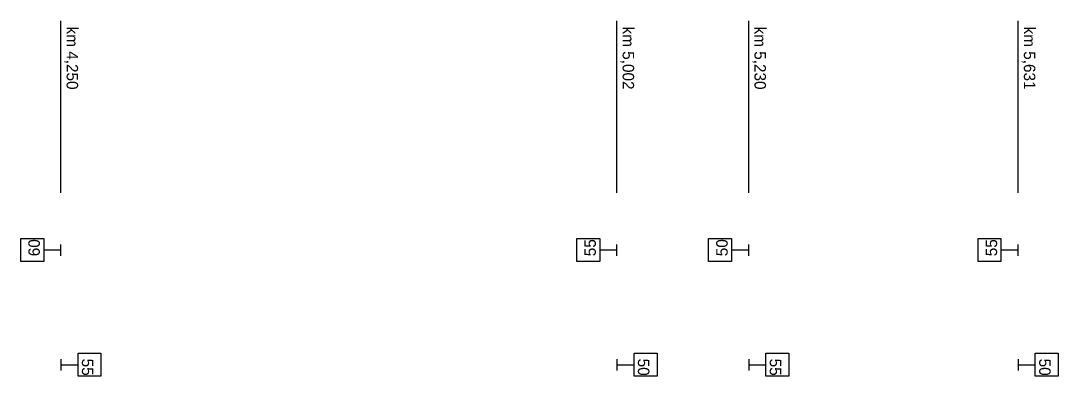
# Model space of a CAD drawing. Extents: x -591 to 5777, y 380 to 2087.
# Drawn here: x 2343 to 2524, y 1988 to 2050 of the extents above; entities that cross this region are included whole.
import ezdxf

# ---------------------------------------------------------------- set-up
doc = ezdxf.new("R2010")
doc.units = 0
doc.layers.add('rychlostník', color=7, linetype='Continuous')

msp = doc.modelspace()

# ---------------------------------------------------------------- linework, layer by layer
at = {"layer": 'rychlostník'}
for p, q in [((2350, 2020), (2350, 2050)), ((2447, 2020), (2447, 2050)), ((2447, 2020), (2447, 2050)), ((2470, 2020), (2470, 2050)), ((2470, 2020), (2470, 2050)), ((2517, 2020), (2517, 2050)), ((2517, 2020), (2517, 2050)), ((2343, 2008), (2343, 2012)), ((2343, 2012), (2347, 2012)), ((2347, 2012), (2347, 2008)), ((2350, 2009), (2350, 2011)), ((2440, 2008), (2440, 2012)), ((2440, 2012), (2444, 2012)), ((2444, 2012), (2444, 2008)), ((2447, 2009), (2447, 2011)), ((2463, 2008), (2463, 2012)), ((2463, 2012), (2467, 2012)), ((2467, 2012), (2467, 2008)), ((2470, 2009), (2470, 2011)), ((2510, 2008), (2510, 2012)), ((2510, 2012), (2514, 2012)), ((2514, 2012), (2514, 2008)), ((2517, 2009), (2517, 2011)), ((2350, 2010), (2347, 2010)), ((2442.33, 2010.09), (2442.33, 2010.09)), ((2447, 2010), (2444, 2010)), ((2465.33, 2010.09), (2465.33, 2010.09)), ((2470, 2010), (2467, 2010)), ((2512.33, 2010.09), (2512.33, 2010.09)), ((2517, 2010), (2514, 2010)), ((2347, 2008), (2343, 2008)), ((2444, 2008), (2440, 2008)), ((2467, 2008), (2463, 2008)), ((2514, 2008), (2510, 2008)), ((2353, 1992), (2357, 1992)), ((2353, 1988), (2353, 1992)), ((2357, 1992), (2357, 1988)), ((2450, 1992), (2454, 1992)), ((2450, 1988), (2450, 1992)), ((2454, 1992), (2454, 1988)), ((2473, 1992), (2477, 1992)), ((2473, 1988), (2473, 1992)), ((2477, 1992), (2477, 1988)), ((2520, 1992), (2524, 1992)), ((2520, 1988), (2520, 1992)), ((2524, 1992), (2524, 1988)), ((2350, 1991), (2350, 1989)), ((2350, 1990), (2353, 1990)), ((2447, 1991), (2447, 1989)), ((2447, 1990), (2450, 1990)), ((2451.67, 1989.91), (2451.67, 1989.91)), ((2470, 1991), (2470, 1989)), ((2470, 1990), (2473, 1990)), ((2474.67, 1989.91), (2474.67, 1989.91)), ((2517, 1991), (2517, 1989)), ((2517, 1990), (2520, 1990)), ((2521.67, 1989.91), (2521.67, 1989.91)), ((2357, 1988), (2353, 1988)), ((2454, 1988), (2450, 1988)), ((2477, 1988), (2473, 1988)), ((2524, 1988), (2520, 1988))]:
    msp.add_line(p, q, dxfattribs=at)

# ---------------------------------------------------------------- texts
for s, rotation, p in [('km 4,250', 270, (2351, 2049)), ('km 5,002', 270, (2448, 2049)), ('km 5,230', 270, (2471, 2049)), ('km 5,631', 270, (2518, 2049)), ('60', 90, (2346.33, 2008.93)), ('55', 90, (2443.33, 2008.93)), ('50', 90, (2466.33, 2008.93)), ('55', 90, (2513.33, 2008.93)), ('55', 270, (2353.67, 1991.07)), ('50', 270, (2450.67, 1991.07)), ('55', 270, (2473.67, 1991.07)), ('50', 270, (2520.67, 1991.07))]:
    msp.add_text(s, height=2, rotation=rotation, dxfattribs=at).set_placement(p)

doc.saveas('drawing.dxf')
